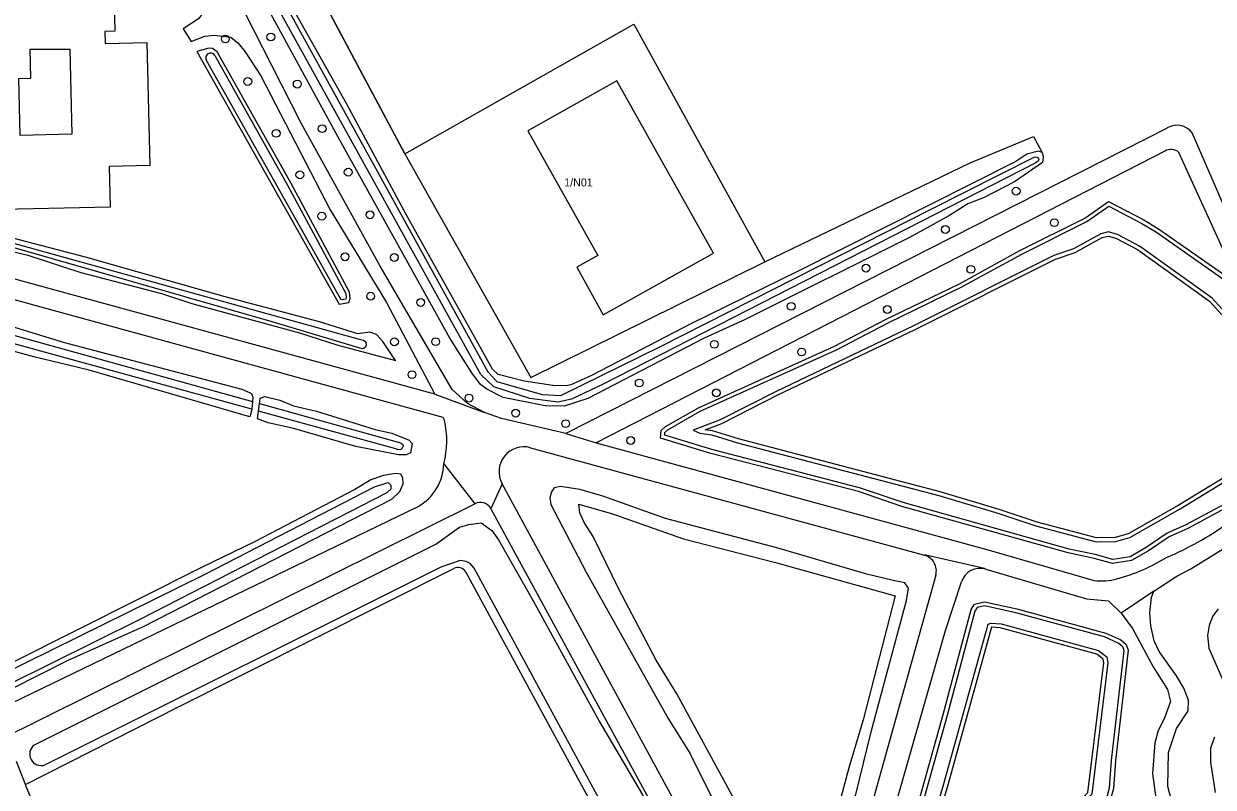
# Model space of a CAD drawing. Extents: x 162791 to 163827, y 385795 to 386523.
# Drawn here: x 163263.1 to 163411.8, y 386372.8 to 386468.3 of the extents above; entities that cross this region are included whole.
import ezdxf

# ---------------------------------------------------------------- set-up
doc = ezdxf.new("R2010")
doc.units = 0
for name, color, linetype in [('IMGEO_Boom', 7, 'Continuous'), ('IMGEO_Erf', 7, 'Continuous'), ('IMGEO_Grasland_overig', 7, 'Continuous'), ('IMGEO_Groenvoorziening', 7, 'Continuous'), ('IMGEO_Hek', 7, 'Continuous'), ('IMGEO_Loofbos', 7, 'Continuous'), ('IMGEO_Pand', 7, 'Continuous'), ('IMGEO_Pand_nummerreeks', 7, 'Continuous'), ('IMGEO_Voetpad_halfverhard', 7, 'Continuous'), ('IMGEO_Waterloop', 7, 'Continuous'), ('IMGEO_Woonerf_open', 7, 'Continuous')]:
    doc.layers.add(name, color=color, linetype=linetype)

msp = doc.modelspace()

# ---------------------------------------------------------------- linework, layer by layer
at = {"layer": 'IMGEO_Boom'}
for centre in [(163288.33, 386466.36), (163294.02, 386466.61), (163291.14, 386461.04), (163297.32, 386460.72), (163294.69, 386454.56), (163300.44, 386455.15), (163303.69, 386449.7), (163297.65, 386449.37), (163387.16, 386447.34), (163300.39, 386444.2), (163306.41, 386444.38), (163378.32, 386442.54), (163391.94, 386443.39), (163303.28, 386439.13), (163309.45, 386439.04), (163368.4, 386437.71), (163381.51, 386437.56), (163306.49, 386434.2), (163312.75, 386433.42), (163359.05, 386432.94), (163371.07, 386432.54), (163309.47, 386428.5), (163314.62, 386428.51), (163349.44, 386428.19), (163360.35, 386427.22), (163311.66, 386424.39), (163340.06, 386423.34), (163318.78, 386421.46), (163349.7, 386422.12), (163324.62, 386419.58), (163330.86, 386418.27), (163338.99, 386416.16)]:
    msp.add_circle(centre, 0.489, dxfattribs=at)
at = {"layer": 'IMGEO_Erf'}
for points in [[(163284.77, 386464.81), (163302.55, 386433.19), (163303.75, 386433.41), (163303.95, 386433.93), (163303.87, 386434.69), (163296.54, 386448.31), (163287.33, 386464.75), (163286.71, 386465.17), (163286.25, 386465.23), (163284.77, 386464.81)], [(163256.4, 386441.07), (163263.63, 386439.31), (163270.28, 386437.15), (163280.34, 386434.52), (163284.16, 386433.3), (163297.59, 386429.63), (163302.25, 386428.13), (163309.6, 386426.17), (163308.02, 386428.53), (163307.23, 386429.41), (163306.39, 386429.71), (163304.87, 386429.49), (163300.11, 386430.99), (163288.33, 386434.12), (163270.86, 386439.09), (163257.26, 386442.61)], [(163240.49, 386436.2), (163241.23, 386436.01), (163246.87, 386434.26), (163260.36, 386430.82), (163268.08, 386428.47), (163290.41, 386422.56), (163291.59, 386422.02), (163291.77, 386421.56), (163291.72, 386421.02)], [(163291.63, 386420.07), (163291.61, 386419.86), (163291.39, 386419.12), (163271.3, 386424.97), (163264.4, 386426.64), (163244.13, 386432.15), (163240.54, 386433.22)], [(163292.59, 386420.77), (163292.67, 386421.44), (163293.27, 386421.66), (163295.13, 386421.22), (163296.87, 386420.5), (163299.71, 386419.82), (163307.04, 386417.55), (163309.16, 386417.07), (163311.32, 386416.21), (163311.68, 386415.79), (163311.46, 386414.61), (163310.92, 386414.37), (163309.98, 386414.37), (163304.62, 386415.41), (163296.73, 386417.7), (163293.67, 386418.38), (163292.37, 386418.88), (163292.48, 386419.83)], [(163239.27, 386373.67), (163241.29, 386374.54), (163244.91, 386376.46), (163247.33, 386377.88), (163268.68, 386388.68), (163278.12, 386392.91), (163309.16, 386408.83), (163310.16, 386409.79), (163310.54, 386410.75), (163310.52, 386411.49), (163310.26, 386411.93), (163309.6, 386412.05), (163308.1, 386411.77), (163306.5, 386411.23), (163304.5, 386410.04), (163291.96, 386403.48), (163285.34, 386400.29), (163261.91, 386388.47), (163247.03, 386381.44), (163236.33, 386376.13)]]:
    msp.add_lwpolyline(points, dxfattribs=at)
at = {"layer": 'IMGEO_Grasland_overig'}
for points in [[(163390.4, 386452.15), (163389.95, 386452.32), (163388.51, 386451.96), (163387.13, 386451.06), (163359.99, 386437.36), (163346.49, 386430.73), (163334.08, 386424.28), (163331.52, 386423.1), (163330.93, 386422.98), (163329.28, 386423.04), (163325.66, 386423.56), (163322.44, 386424.42), (163321.74, 386425.06), (163310.95, 386444.42), (163303.5, 386458.22), (163288.03, 386485.77), (163282.04, 386498.02)], [(163310.76, 386451.99), (163317.42, 386440.16), (163326.5, 386424.02), (163355.74, 386438.49)]]:
    msp.add_lwpolyline(points, dxfattribs=at)
at = {"layer": 'IMGEO_Groenvoorziening'}
for points in [[(163349.01, 386414.55), (163342.73, 386416.47), (163342.78, 386417.39), (163343.36, 386417.9), (163347.46, 386420.26), (163364.47, 386427.95), (163370.84, 386431.28), (163380.07, 386435.75), (163387.63, 386439.91), (163395.73, 386443.95), (163398.7, 386446.04), (163403.11, 386443.75), (163404.97, 386442.61), (163413.48, 386436.66)], [(163416.4, 386409.35), (163408.6, 386405.15), (163406.29, 386404.12), (163403.69, 386402.36), (163401.56, 386401.15), (163399.2, 386400.76), (163396.92, 386401.42), (163393.67, 386402.1), (163372.89, 386407.92), (163367.44, 386409.78), (163349.01, 386414.55)], [(163263.34, 386373.16), (163282.46, 386382.87), (163316.9, 386400.17)], [(163318.38, 386399.71), (163337.09, 386365.23), (163344.22, 386352.43), (163344.08, 386352.31), (163344.71, 386351.21)], [(163372.89, 386355.39), (163371.88, 386355.49), (163371.39, 386355.89), (163371.19, 386356.67), (163371.29, 386357.72), (163378.04, 386381.9), (163381.53, 386395.02), (163381.96, 386395.7), (163383.21, 386395.99), (163387.23, 386395.1), (163398.37, 386392.06), (163400.25, 386391.22), (163400.93, 386390.67), (163401.17, 386389.94), (163399.58, 386376.11), (163399.33, 386372.66), (163398.68, 386370.22), (163397.96, 386369.5), (163390.68, 386365.33), (163383.64, 386361.5), (163380.38, 386359.28), (163373.93, 386355.71), (163372.89, 386355.39)]]:
    msp.add_lwpolyline(points, dxfattribs=at)
msp.add_arc((163317.4, 386399.18), 1.11, 28.4552, 116.6727, dxfattribs=at)
at = {"layer": 'IMGEO_Hek'}
for points in [[(163310.76, 386451.99), (163287.56, 386495.54)], [(163310.76, 386451.99), (163339.39, 386468.21), (163352.42, 386444.53), (163355.74, 386438.49)], [(163355.74, 386438.49), (163369.4, 386445.07), (163381.41, 386450.86), (163389.32, 386454.15), (163390.4, 386452.15)], [(163310.76, 386451.99), (163317.42, 386440.16), (163326.5, 386424.02), (163355.74, 386438.49)]]:
    msp.add_lwpolyline(points, dxfattribs=at)
at = {"layer": 'IMGEO_Loofbos'}
for points in [[(163390.4, 386452.15), (163390.53, 386451.64), (163390.47, 386450.92), (163386.95, 386448.48), (163383.17, 386446.54), (163381.13, 386445.74), (163378.85, 386444.31), (163373.93, 386441.57), (163353.21, 386431.26), (163348.19, 386428.97), (163333.65, 386421.4), (163330.68, 386420.46), (163328.3, 386420.5), (163323.06, 386421.52), (163321, 386422.56), (163320.24, 386423.16), (163319.12, 386424.62), (163316.4, 386428.97), (163302.44, 386454.09), (163286.59, 386483.15), (163280.86, 386494.17), (163279.71, 386498)], [(163287.56, 386495.54), (163310.76, 386451.99)], [(163310.76, 386451.99), (163339.39, 386468.21), (163352.42, 386444.53), (163355.74, 386438.49)], [(163355.74, 386438.49), (163369.4, 386445.07), (163381.41, 386450.86), (163389.32, 386454.15), (163390.4, 386452.15)], [(163399.55, 386404.01), (163397.21, 386403.97), (163389.77, 386405.95), (163385.04, 386407.55), (163377.65, 386409.76), (163352.46, 386416.35), (163349.22, 386417.36), (163348.29, 386417.5), (163350.39, 386418.29), (163357.39, 386421.86), (163374.54, 386430.04), (163392.08, 386438.82), (163394.54, 386439.68), (163397.92, 386441.53), (163398.71, 386441.72), (163399.63, 386441.47), (163402.31, 386440.03), (163411.34, 386433.58), (163412.85, 386431.87)], [(163416.22, 386413.41), (163407.39, 386408.03), (163401.15, 386404.47), (163399.55, 386404.01)], [(163412.42, 386395.1), (163411.72, 386394.14), (163411.3, 386393.01), (163411.06, 386391.77), (163411.24, 386390.19), (163413.74, 386384.47)], [(163374.62, 386359.49), (163384.19, 386365.01), (163387.86, 386367.53), (163395.53, 386371.52), (163396.12, 386372.14), (163398.1, 386388.35), (163398.03, 386388.82), (163397.24, 386389.44), (163385.18, 386392.74), (163384.08, 386392.81), (163378.54, 386372.79), (163374.69, 386360.19), (163374.62, 386359.49)], [(163411.93, 386379.05), (163411.47, 386377.69), (163411.43, 386375.93), (163412.05, 386372.15)]]:
    msp.add_lwpolyline(points, dxfattribs=at)
at = {"layer": 'IMGEO_Pand'}
for points in [[(163261.34, 386479.94), (163269.15, 386480.12), (163269.26, 386475.06), (163274.34, 386475.18), (163274.52, 386467.33), (163273.27, 386467.31), (163273.3, 386465.78), (163278.53, 386465.9), (163278.88, 386450.54), (163273.83, 386450.42), (163273.94, 386445.35), (163258.52, 386445)], [(163263.95, 386465.1), (163268.91, 386465.08), (163269.15, 386454.45), (163262.68, 386454.3), (163262.52, 386461.44), (163264.04, 386461.47), (163263.95, 386465.1)], [(163349.34, 386439.6), (163337.27, 386461.13), (163326.14, 386454.89), (163334.89, 386439.29), (163332.24, 386437.81), (163335.56, 386431.87), (163349.34, 386439.6)]]:
    msp.add_lwpolyline(points, dxfattribs=at)
at = {"layer": 'IMGEO_Voetpad_halfverhard'}
for points in [[(163273.49, 386497.3), (163281.33, 386481.61), (163285.91, 386473.57), (163286.21, 386471.47), (163285.85, 386470.05), (163284.97, 386468.89), (163283.05, 386467.63), (163284.05, 386466.03), (163285.75, 386466.71), (163286.99, 386466.85), (163289.01, 386466.59), (163289.95, 386465.83), (163290.8, 386464.75), (163292.76, 386461.77), (163301.43, 386445.01), (163308.47, 386433.41), (163314.53, 386421.97)], [(163320.72, 386419.68), (163318.58, 386420.79), (163316.66, 386422.54), (163307.69, 386437.97), (163297.82, 386455.83), (163289.41, 386472.43), (163285.31, 386479.73), (163276.02, 386497.56)], [(163406.03, 386455.23), (163330.9, 386417.04)], [(163456.37, 386356.49), (163447.74, 386373.25), (163440.05, 386389.07), (163435.81, 386397.11), (163423.61, 386421.35), (163409.15, 386454.61)], [(163405.75, 386452.34), (163334.67, 386415.88)], [(163422.17, 386420.05), (163407.51, 386452.18)], [(163314.53, 386421.97), (163254.86, 386438.3)], [(163315.72, 386418.7), (163315.55, 386419.03), (163254.2, 386435.89)], [(163314.53, 386421.97), (163320.72, 386419.68)], [(163330.9, 386417.04), (163322.86, 386418.9), (163320.72, 386419.68)], [(163330.9, 386417.04), (163334.67, 386415.88)], [(163326.47, 386415.26), (163375.7, 386401.82)], [(163334.67, 386415.88), (163383.51, 386402.54), (163396.91, 386398.67)], [(163315.64, 386413.25), (163319.5, 386408.26)], [(163322.91, 386410.76), (163321.53, 386407.62)], [(163358.16, 386346.28), (163351.9, 386357.4), (163322.91, 386410.76)], [(163404.38, 386397.31), (163407.24, 386399.2), (163408.98, 386400.1), (163413.92, 386403.16), (163418.3, 386406.16), (163420.24, 386407.74), (163422.84, 386409.51), (163424.38, 386410.19), (163425.3, 386410.19), (163425.92, 386410.03), (163427.12, 386408.93)], [(163253.99, 386379.64), (163312.42, 386407.89)], [(163259.74, 386378.56), (163319.5, 386408.26)], [(163321.53, 386407.62), (163361.43, 386334.34)], [(163383.36, 386400.08), (163383.22, 386400.17), (163375.89, 386401.82), (163375.7, 386401.82)], [(163383.36, 386400.08), (163395.95, 386396.35), (163398.7, 386396.11), (163400.28, 386394.55)], [(163377.11, 386399.33), (163362.47, 386346.79)], [(163370.24, 386364.13), (163378.33, 386392.42), (163380.33, 386398.49)], [(163404.38, 386397.31), (163400.28, 386394.55)], [(163407.15, 386368.95), (163406.11, 386372.91), (163406.22, 386377.15), (163407.22, 386380.17), (163408.64, 386382.37), (163408.68, 386383.69), (163408.1, 386385.19), (163407.22, 386386.73), (163405.02, 386389.79), (163404.4, 386391.09), (163403.98, 386392.97), (163403.88, 386394.67), (163404.08, 386396.53), (163404.38, 386397.31)], [(163400.28, 386394.55), (163401.7, 386392.65), (163404.28, 386387.87), (163406.06, 386385.03), (163406.46, 386383.51), (163405.68, 386381.35), (163404.92, 386379.89), (163404.5, 386378.35), (163404.21, 386374.53), (163404.83, 386369.91)]]:
    msp.add_lwpolyline(points, dxfattribs=at)
for centre, radius, start, end in [((163407.26, 386453.24), 2.34, 35.952, 121.6825), ((163406.51, 386450.95), 1.59, 50.9622, 118.5844), ((163304.61, 386416.14), 11.4, 345.2973, 12.9799), ((163325.65, 386412.25), 3.12, 74.7371, 208.5142), ((163309.25, 386413.44), 6.39, 299.7027, 358.2881), ((163320.19, 386406.89), 1.53, 28.3369, 116.6147), ((163389.1, 386440.51), 42.48, 293.5118, 305.0018), ((163375.17, 386399.87), 2.02, 344.4207, 74.7265), ((163393.09, 386422.96), 25.01, 285.4427, 301.2067), ((163382.66, 386397.72), 2.46, 73.489, 161.7676), ((163397.91, 386405.45), 6.85, 261.6025, 285.5728)]:
    msp.add_arc(centre, radius, start, end, dxfattribs=at)
at = {"layer": 'IMGEO_Waterloop'}
for points in [[(163295.27, 386471.72), (163321.15, 386424.73), (163322.27, 386423.52), (163327.94, 386421.89), (163330.27, 386421.8), (163342.71, 386427.91), (163376.56, 386445.09), (163389.41, 386451.6), (163389.59, 386451.62), (163389.75, 386451.6), (163389.83, 386451.56), (163389.96, 386451.37), (163389.98, 386451.26), (163389.9, 386451.08), (163389.63, 386450.86), (163335.53, 386423.19), (163331.6, 386421.32), (163329.89, 386420.96), (163326.4, 386421.4), (163321.87, 386422.87), (163320.26, 386424.4), (163286.13, 386486.1)], [(163287.02, 386464.28), (163296.1, 386448.07), (163303.38, 386434.54), (163303.44, 386434), (163303.38, 386433.85), (163302.81, 386433.75), (163285.97, 386463.69)], [(163373.04, 386408.4), (163367.58, 386410.26), (163349.15, 386415.03), (163343.25, 386416.83), (163343.27, 386417.15), (163343.65, 386417.49), (163347.69, 386419.81), (163364.69, 386427.5), (163371.07, 386430.83), (163380.3, 386435.31), (163387.86, 386439.46), (163395.98, 386443.52), (163398.74, 386445.46), (163402.86, 386443.31), (163404.7, 386442.19), (163413.12, 386436.3)], [(163257.02, 386442.17), (163305.04, 386428.81), (163305.58, 386428.69), (163305.78, 386428.56), (163305.89, 386428.41), (163305.95, 386428.1), (163305.84, 386427.81), (163305.69, 386427.7), (163305.44, 386427.62), (163294.17, 386431.01), (163261.05, 386440.48), (163256.72, 386441.64)], [(163413.27, 386432.15), (163411.67, 386433.95), (163402.58, 386440.45), (163399.82, 386441.93), (163398.72, 386442.23), (163397.74, 386442), (163394.34, 386440.14), (163391.88, 386439.28), (163374.32, 386430.49), (163357.17, 386422.3), (163350.19, 386418.75), (163346.81, 386417.47), (163347.63, 386417.09), (163349.11, 386416.87), (163352.33, 386415.87), (163377.52, 386409.28), (163384.89, 386407.07), (163389.63, 386405.47), (163397.15, 386403.47), (163399.63, 386403.51), (163401.35, 386404.01), (163407.64, 386407.6), (163416.46, 386412.98)], [(163240.51, 386435.26), (163291.72, 386421.02)], [(163291.63, 386420.07), (163240.52, 386434.11)], [(163291.72, 386421.02), (163291.63, 386420.07)], [(163292.48, 386419.83), (163292.59, 386420.77)], [(163292.59, 386420.77), (163309.62, 386416.04), (163309.98, 386415.94), (163310.3, 386415.83), (163310.51, 386415.67), (163310.56, 386415.57), (163310.57, 386415.47), (163310.45, 386415.19), (163310.27, 386415.04), (163309.95, 386415.01), (163309.66, 386415.11), (163292.48, 386419.83)], [(163308.66, 386410.86), (163308.35, 386410.8), (163306.92, 386410.32), (163285.79, 386399.39), (163247.47, 386380.54), (163238.46, 386376.07)], [(163239.1, 386374.69), (163240.86, 386375.44), (163244.42, 386377.33), (163277.69, 386393.82), (163308.57, 386409.66), (163309.04, 386410.11)], [(163366.58, 386369.67), (163369.07, 386379.89), (163373.47, 386396.16), (163373.71, 386397.7), (163373.25, 386398.36), (163371.79, 386398.66), (163368.52, 386399.46), (163357.24, 386402.73), (163343.35, 386406.4), (163335.49, 386409.2), (163332.63, 386410.02), (163330.23, 386410.42), (163329.41, 386410.22), (163329.09, 386409.74), (163328.89, 386409), (163329.01, 386408.16), (163333.41, 386399.7), (163343.66, 386381.38), (163346.37, 386377.06), (163349.15, 386371.54)], [(163416.14, 386409.78), (163408.38, 386405.6), (163406.05, 386404.56), (163403.43, 386402.79), (163401.39, 386401.63), (163399.23, 386401.27), (163397.05, 386401.91), (163393.79, 386402.59), (163373.04, 386408.4)], [(163360.7, 386356.76), (163360.16, 386356.76), (163359.08, 386357.98), (163355.47, 386365.08), (163351.91, 386371.3), (163344.74, 386384.5), (163342.16, 386388.7), (163337.48, 386397.64), (163334.29, 386404.16), (163333.17, 386405.9), (163332.63, 386407.1), (163332.49, 386408.18), (163336.71, 386407), (163345.58, 386403.88), (163357.08, 386400.91), (163372.03, 386396.72), (163368.05, 386381.23), (163366.25, 386375.23), (163364.14, 386367.29), (163361.84, 386359.58), (163361.04, 386357.36), (163360.7, 386356.76)], [(163264.42, 386378.07), (163314.65, 386403.19), (163317.59, 386405.33), (163318.75, 386405.67), (163320.29, 386405.87), (163321.63, 386404.91), (163322.45, 386403.73), (163326.79, 386396.13), (163335.06, 386381.07), (163340.47, 386371.85), (163347.8, 386358.26), (163357.08, 386341.84), (163361.09, 386334.28)], [(163357.39, 386331.25), (163355.29, 386334.65), (163340.01, 386362.19), (163319.41, 386400.19), (163318.95, 386400.77), (163318.45, 386401.03), (163317.69, 386401.17), (163315.27, 386400.33), (163266.22, 386375.8), (163265.77, 386375.59)], [(163373.74, 386356.17), (163380.12, 386359.71), (163383.38, 386361.93), (163390.44, 386365.76), (163397.66, 386369.9), (163398.24, 386370.48), (163398.84, 386372.74), (163399.08, 386376.16), (163400.66, 386389.89), (163400.5, 386390.37), (163399.98, 386390.79), (163398.2, 386391.59), (163387.11, 386394.62), (163383.21, 386395.48), (163382.27, 386395.26), (163381.99, 386394.82), (163378.52, 386381.76), (163371.78, 386357.63), (163371.7, 386356.71), (163371.84, 386356.17), (163372.08, 386355.97), (163372.84, 386355.89), (163373.74, 386356.17)], [(163374.04, 386358.71), (163374.2, 386360.29), (163378.06, 386372.93), (163383.67, 386393.18), (163383.99, 386393.32), (163385.27, 386393.24), (163397.46, 386389.89), (163398.5, 386389.09), (163398.6, 386388.35), (163396.6, 386371.92), (163395.84, 386371.12), (163388.12, 386367.1), (163384.46, 386364.59), (163374.44, 386358.81), (163374.04, 386358.71)]]:
    msp.add_lwpolyline(points, dxfattribs=at)
for centre, radius, start, end in [((163286.49, 386463.99), 0.6, 29.3005, 209.337), ((163308.48, 386410.3), 0.59, 341.5316, 72.873), ((163265.32, 386376.95), 1.43, 128.606, 288.2515)]:
    msp.add_arc(centre, radius, start, end, dxfattribs=at)
at = {"layer": 'IMGEO_Woonerf_open'}
for points in [[(163263.34, 386373.16), (163262.23, 386376.04)], [(163265.34, 386368.45), (163263.4, 386372.99), (163263.34, 386373.16)]]:
    msp.add_lwpolyline(points, dxfattribs=at)

# ---------------------------------------------------------------- texts
at = {"layer": 'IMGEO_Pand_nummerreeks'}
msp.add_text('1/N01', height=1, dxfattribs=at).set_placement((163330.68, 386447.92))

doc.saveas('drawing.dxf')
